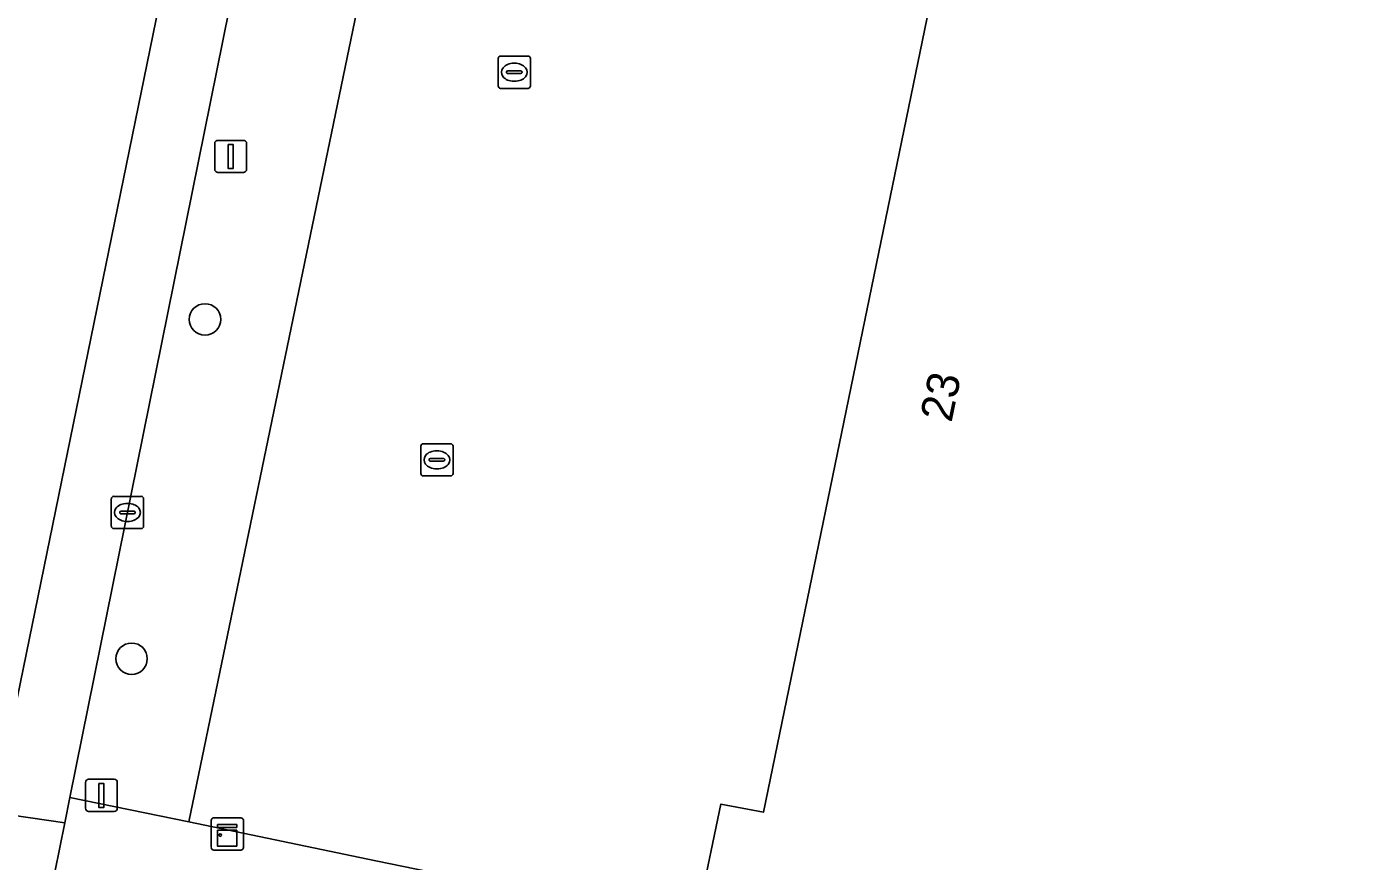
# Model space of a CAD drawing. Extents: x 157692 to 159674, y 381452 to 383291.
# Drawn here: x 158535.67 to 158577.39, y 382134.66 to 382160.56 of the extents above; entities that cross this region are included whole.
import ezdxf

# ---------------------------------------------------------------- set-up
doc = ezdxf.new("R2010")
doc.units = 0
for name, color, linetype in [('IMGEO_Boom', 7, 'Continuous'), ('IMGEO_Erf', 7, 'Continuous'), ('IMGEO_Kast', 7, 'Continuous'), ('IMGEO_Kolk', 7, 'Continuous'), ('IMGEO_Lichtmast', 7, 'Continuous'), ('IMGEO_Pand', 7, 'Continuous'), ('IMGEO_Pand_nummerreeks', 7, 'Continuous'), ('IMGEO_Rijbaan_lokaal_gesloten', 7, 'Continuous'), ('IMGEO_Voetpad_open', 7, 'Continuous')]:
    doc.layers.add(name, color=color, linetype=linetype)

msp = doc.modelspace()

# ---------------------------------------------------------------- linework, layer by layer
at = {"layer": 'IMGEO_Boom'}
for centre in [(158541.206, 382151.477), (158538.925, 382140.939)]:
    msp.add_circle(centre, 0.489, dxfattribs=at)
at = {"layer": 'IMGEO_Erf'}
msp.add_lwpolyline([(158556.642, 382213.448), (158553.461, 382197.47), (158549.725, 382179.858), (158546.937, 382165.963), (158540.709, 382135.881), (158546.509, 382134.668), (158563.223, 382131.236), (158563.315, 382131.7), (158554.772, 382133.456), (158554.818, 382133.659), (158556.568, 382133.298), (158557.225, 382136.428), (158558.548, 382136.172), (158564.131, 382163.272), (158575.023, 382161.028), (158577.294, 382172.047), (158561.216, 382175.361), (158565.247, 382195.087), (158556.948, 382196.783), (158558.961, 382206.635), (158560.882, 382216.032)], dxfattribs=at)
at = {"layer": 'IMGEO_Kast'}
for p, q in [((158541.399, 382135.074), (158541.399, 382135.915)), ((158541.399, 382135.915), (158541.399, 382135.074)), ((158541.474, 382135.999), (158542.315, 382135.999)), ((158542.315, 382135.999), (158541.474, 382135.999)), ((158542.399, 382135.924), (158542.399, 382135.083)), ((158542.399, 382135.083), (158542.399, 382135.924)), ((158542.324, 382134.999), (158541.483, 382134.999)), ((158541.483, 382134.999), (158542.324, 382134.999))]:
    msp.add_line(p, q, dxfattribs=at)
for points in [[(158541.594, 382135.789), (158542.194, 382135.789), (158542.194, 382135.704), (158541.594, 382135.704), (158541.594, 382135.789)], [(158541.594, 382135.614), (158542.194, 382135.614), (158542.194, 382135.125), (158541.594, 382135.125), (158541.594, 382135.614)]]:
    msp.add_lwpolyline(points, dxfattribs=at)
msp.add_circle((158541.678, 382135.463), 0.0377, dxfattribs=at)
for centre, start, end in [((158541.477, 382135.921), 92.4484, 184.2845), ((158541.477, 382135.921), 92.4484, 184.2845), ((158542.321, 382135.921), 2.4484, 94.2845), ((158542.321, 382135.921), 2.4484, 94.2845), ((158541.477, 382135.077), 182.4484, 274.2845), ((158541.477, 382135.077), 182.4484, 274.2845), ((158542.321, 382135.077), 272.4484, 4.2845), ((158542.321, 382135.077), 272.4484, 4.2845)]:
    msp.add_arc(centre, 0.0779, start, end, dxfattribs=at)
at = {"layer": 'IMGEO_Kolk'}
for p, q in [((158550.31, 382158.728), (158550.31, 382159.58)), ((158550.385, 382159.654), (158551.237, 382159.654)), ((158550.798, 382159.434), (158550.823, 382159.434)), ((158551.311, 382159.58), (158551.311, 382158.728)), ((158550.569, 382159.148), (158550.569, 382159.16)), ((158551.007, 382159.111), (158550.609, 382159.111)), ((158550.612, 382159.197), (158551.01, 382159.197)), ((158551.053, 382159.16), (158551.053, 382159.148)), ((158551.237, 382158.654), (158550.385, 382158.654)), ((158550.821, 382158.874), (158550.796, 382158.874)), ((158547.907, 382146.691), (158547.907, 382147.543)), ((158547.982, 382147.617), (158548.834, 382147.617)), ((158548.395, 382147.397), (158548.42, 382147.397)), ((158548.908, 382147.543), (158548.908, 382146.691)), ((158548.166, 382147.111), (158548.166, 382147.123)), ((158548.604, 382147.074), (158548.206, 382147.074)), ((158548.209, 382147.16), (158548.607, 382147.16)), ((158548.65, 382147.123), (158548.65, 382147.111)), ((158548.834, 382146.617), (158547.982, 382146.617)), ((158548.418, 382146.837), (158548.393, 382146.837)), ((158538.297, 382145.058), (158538.297, 382145.91)), ((158538.372, 382145.984), (158539.224, 382145.984)), ((158538.785, 382145.764), (158538.81, 382145.764)), ((158539.298, 382145.91), (158539.298, 382145.058)), ((158538.556, 382145.478), (158538.556, 382145.49)), ((158538.994, 382145.441), (158538.596, 382145.441)), ((158538.599, 382145.527), (158538.997, 382145.527)), ((158539.04, 382145.49), (158539.04, 382145.478)), ((158539.224, 382144.984), (158538.372, 382144.984)), ((158538.808, 382145.204), (158538.783, 382145.204))]:
    msp.add_line(p, q, dxfattribs=at)
for points in [[(158550.31, 382158.728), (158550.31, 382159.58)], [(158550.385, 382159.654), (158551.237, 382159.654)], [(158551.311, 382159.58), (158551.311, 382158.728)], [(158551.237, 382158.654), (158550.385, 382158.654)], [(158547.907, 382146.691), (158547.907, 382147.543)], [(158547.982, 382147.617), (158548.834, 382147.617)], [(158548.908, 382147.543), (158548.908, 382146.691)], [(158548.834, 382146.617), (158547.982, 382146.617)], [(158538.297, 382145.058), (158538.297, 382145.91)], [(158538.372, 382145.984), (158539.224, 382145.984)], [(158539.298, 382145.91), (158539.298, 382145.058)], [(158539.224, 382144.984), (158538.372, 382144.984)]]:
    msp.add_lwpolyline(points, dxfattribs=at)
for centre, radius, start, end in [((158550.387, 382159.578), 0.0765, 91.552, 178.448), ((158550.387, 382159.578), 0.0765, 91.552, 178.448), ((158551.235, 382159.578), 0.0765, 1.552, 88.448), ((158551.235, 382159.578), 0.0765, 1.552, 88.448), ((158550.609, 382159.157), 0.0403, 85.8775, 175.7526), ((158550.606, 382159.147), 0.0366, 178.938, 274.7102), ((158551.01, 382159.154), 0.043, 264.8664, 352.4533), ((158551.014, 382159.159), 0.0386, 1.7309, 96.639), ((158550.387, 382158.73), 0.0765, 181.552, 268.448), ((158550.387, 382158.73), 0.0765, 181.552, 268.448), ((158551.235, 382158.73), 0.0765, 271.552, 358.448), ((158551.235, 382158.73), 0.0765, 271.552, 358.448), ((158547.984, 382147.541), 0.0765, 91.552, 178.448), ((158547.984, 382147.541), 0.0765, 91.552, 178.448), ((158548.832, 382147.541), 0.0765, 1.552, 88.448), ((158548.832, 382147.541), 0.0765, 1.552, 88.448), ((158548.206, 382147.12), 0.0403, 85.8775, 175.7526), ((158548.203, 382147.11), 0.0366, 178.938, 274.7102), ((158548.607, 382147.117), 0.043, 264.8664, 352.4533), ((158548.611, 382147.122), 0.0386, 1.7309, 96.639), ((158547.984, 382146.693), 0.0765, 181.552, 268.448), ((158547.984, 382146.693), 0.0765, 181.552, 268.448), ((158548.832, 382146.693), 0.0765, 271.552, 358.448), ((158548.832, 382146.693), 0.0765, 271.552, 358.448), ((158538.374, 382145.908), 0.0765, 91.552, 178.448), ((158538.374, 382145.908), 0.0765, 91.552, 178.448), ((158539.222, 382145.908), 0.0765, 1.552, 88.448), ((158539.222, 382145.908), 0.0765, 1.552, 88.448), ((158538.596, 382145.487), 0.0403, 85.8775, 175.7526), ((158538.593, 382145.477), 0.0366, 178.938, 274.7102), ((158538.997, 382145.484), 0.043, 264.8664, 352.4533), ((158539.001, 382145.489), 0.0386, 1.7309, 96.639), ((158538.374, 382145.06), 0.0765, 181.552, 268.448), ((158538.374, 382145.06), 0.0765, 181.552, 268.448), ((158539.222, 382145.06), 0.0765, 271.552, 358.448), ((158539.222, 382145.06), 0.0765, 271.552, 358.448)]:
    msp.add_arc(centre, radius, start, end, dxfattribs=at)
for centre, major_axis, ratio, start_param, end_param in [((158550.797, 382159.154), (-0.387, 0.002), 0.722429, 4.712389, 7.853982), ((158550.822, 382159.154), (-0.39, 0.002), 0.717154, 1.570796, 4.712389), ((158548.394, 382147.117), (-0.387, 0.002), 0.722429, 4.712389, 7.853982), ((158548.419, 382147.117), (-0.39, 0.002), 0.717154, 1.570796, 4.712389), ((158538.784, 382145.484), (-0.387, 0.002), 0.722429, 4.712389, 7.853982), ((158538.809, 382145.484), (-0.39, 0.002), 0.717154, 1.570796, 4.712389)]:
    msp.add_ellipse(centre, major_axis=major_axis, ratio=ratio, start_param=start_param, end_param=end_param, dxfattribs=at)
at = {"layer": 'IMGEO_Lichtmast'}
for p, q in [((158541.508, 382156.139), (158541.508, 382156.939)), ((158541.508, 382156.939), (158541.508, 382156.139)), ((158541.608, 382157.039), (158542.398, 382157.039)), ((158542.398, 382157.039), (158541.608, 382157.039)), ((158542.498, 382156.939), (158542.498, 382156.139)), ((158542.498, 382156.139), (158542.498, 382156.939)), ((158542.398, 382156.039), (158541.608, 382156.039)), ((158541.608, 382156.039), (158542.398, 382156.039)), ((158537.493, 382136.296), (158537.493, 382137.096)), ((158537.493, 382137.096), (158537.493, 382136.296)), ((158537.593, 382137.196), (158538.383, 382137.196)), ((158538.383, 382137.196), (158537.593, 382137.196)), ((158538.483, 382137.096), (158538.483, 382136.296)), ((158538.483, 382136.296), (158538.483, 382137.096)), ((158538.383, 382136.196), (158537.593, 382136.196)), ((158537.593, 382136.196), (158538.383, 382136.196))]:
    msp.add_line(p, q, dxfattribs=at)
for points in [[(158541.928, 382156.914), (158542.078, 382156.914), (158542.078, 382156.164), (158541.928, 382156.164), (158541.928, 382156.914)], [(158537.913, 382137.071), (158538.063, 382137.071), (158538.063, 382136.321), (158537.913, 382136.321), (158537.913, 382137.071)]]:
    msp.add_lwpolyline(points, dxfattribs=at)
for centre, start, end in [((158541.608, 382156.939), 90, 180), ((158541.608, 382156.939), 90, 180), ((158542.398, 382156.939), 0, 90), ((158542.398, 382156.939), 360, 90), ((158541.608, 382156.139), 180, 270), ((158541.608, 382156.139), 180, 270), ((158542.398, 382156.139), 270, 0), ((158542.398, 382156.139), 270, 0), ((158537.593, 382137.096), 90, 180), ((158537.593, 382137.096), 90, 180), ((158538.383, 382137.096), 0, 90), ((158538.383, 382137.096), 360, 90), ((158537.593, 382136.296), 180, 270), ((158537.593, 382136.296), 180, 270), ((158538.383, 382136.296), 270, 0), ((158538.383, 382136.296), 270, 0)]:
    msp.add_arc(centre, 0.1, start, end, dxfattribs=at)
at = {"layer": 'IMGEO_Pand'}
msp.add_lwpolyline([(158617.909, 382164.108), (158577.294, 382172.047), (158575.023, 382161.028), (158564.131, 382163.272), (158558.548, 382136.172), (158557.225, 382136.428), (158556.568, 382133.298), (158554.818, 382133.659), (158554.772, 382133.456), (158563.315, 382131.7), (158563.223, 382131.236), (158573.743, 382129.079), (158604.33, 382122.808), (158609.261, 382121.797)], close=True, dxfattribs=at)
at = {"layer": 'IMGEO_Rijbaan_lokaal_gesloten'}
for points in [[(158566.717, 382304.975), (158570.119, 382321.454), (158566.644, 382322.187), (158547.202, 382227.455), (158542.075, 382202.135), (158534.877, 382167.21), (158528.747, 382136.998), (158534.64, 382136.161), (158544.988, 382186.707), (158554.178, 382231.666)], [(158563.237, 382275.98), (158554.178, 382231.666), (158544.988, 382186.707), (158534.64, 382136.161), (158536.85, 382135.847), (158537.008, 382136.63), (158543.098, 382166.746), (158549.561, 382198.266), (158555.39, 382226.63), (158560.201, 382250.104)], [(158536.539, 382134.312), (158536.85, 382135.847), (158534.64, 382136.161), (158528.747, 382136.998), (158528.176, 382132.862), (158527.12, 382128.965), (158538.948, 382126.544)]]:
    msp.add_lwpolyline(points, dxfattribs=at)
at = {"layer": 'IMGEO_Voetpad_open'}
msp.add_lwpolyline([(158546.937, 382165.963), (158543.098, 382166.746), (158537.008, 382136.63), (158540.709, 382135.881)], close=True, dxfattribs=at)
msp.add_lwpolyline([(158604.33, 382122.808), (158573.743, 382129.079), (158563.223, 382131.236), (158546.509, 382134.668), (158540.709, 382135.881), (158537.008, 382136.63), (158536.85, 382135.847), (158536.539, 382134.312)], dxfattribs=at)

# ---------------------------------------------------------------- texts
at = {"layer": 'IMGEO_Pand_nummerreeks'}
msp.add_text('23', height=1, rotation=78.3591, dxfattribs=at).set_placement((158564.386, 382148.254))

doc.saveas('drawing.dxf')
